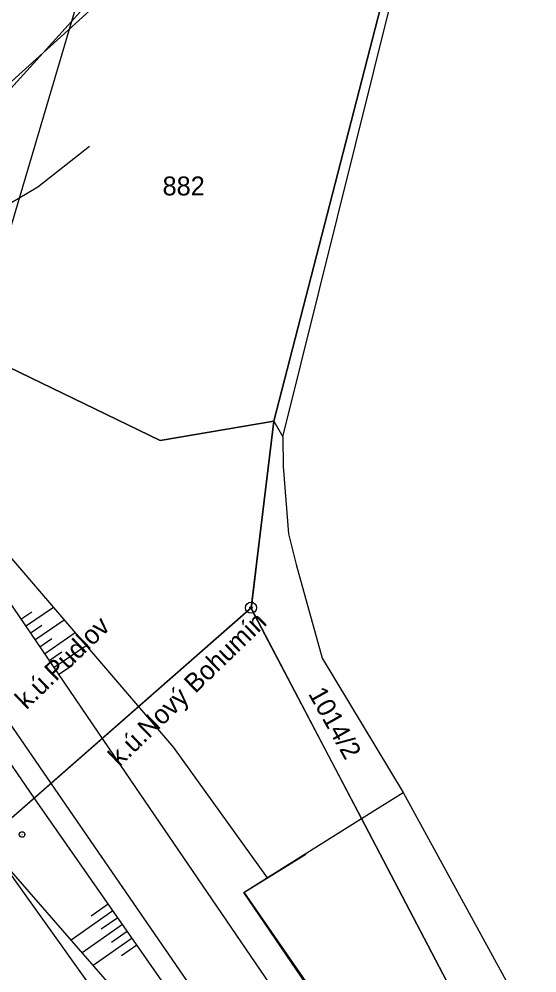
# Model space of a CAD drawing. Extents: x -469926 to -462499, y -1098642 to -1092733.
# Drawn here: x -465515.9 to -465469.3, y -1094927.6 to -1094841.9 of the extents above; entities that cross this region are included whole.
import ezdxf

# ---------------------------------------------------------------- set-up
doc = ezdxf.new("R2010")
doc.units = 0
for name, color, linetype in [('Vrstva 1', 7, 'Continuous'), ('Vrstva 10', 7, 'Continuous'), ('Vrstva 13', 7, 'Continuous'), ('Vrstva 14', 7, 'Continuous'), ('Vrstva 24', 7, 'Continuous'), ('Vrstva 4', 7, 'Continuous'), ('Vrstva 46', 7, 'Continuous'), ('Vrstva 48', 7, 'Continuous'), ('Vrstva 50', 7, 'Continuous'), ('Vrstva 6', 7, 'Continuous'), ('Vrstva 60', 7, 'Continuous'), ('Vrstva 8', 7, 'Continuous')]:
    doc.layers.add(name, color=color, linetype=linetype)

msp = doc.modelspace()

# ---------------------------------------------------------------- linework, layer by layer
at = {"layer": 'Vrstva 1'}
for p, q in [((-465513.71, -1094844.88), (-465507.9, -1094839.62)), ((-465530.47, -1094860.04), (-465513.71, -1094844.88)), ((-465503.18, -1094879.73), (-465516.78, -1094873.13)), ((-465492.98, -1094877.99), (-465503.18, -1094879.73)), ((-465492.98, -1094877.99), (-465492.15, -1094879.38)), ((-465492.15, -1094879.38), (-465492.13, -1094882.07)), ((-465492.13, -1094882.07), (-465491.64, -1094888.11)), ((-465491.64, -1094888.11), (-465490.96, -1094890.86)), ((-465490.96, -1094890.86), (-465488.63, -1094899.27)), ((-465485.09, -1094913.7), (-465495.02, -1094894.75)), ((-465488.63, -1094899.27), (-465481.34, -1094911.35)), ((-465485.09, -1094913.7), (-465481.34, -1094911.35)), ((-465481.34, -1094911.35), (-465461.75, -1094947.14)), ((-465495.65, -1094920.32), (-465485.09, -1094913.7)), ((-465468.49, -1094945.38), (-465485.09, -1094913.7)), ((-465430.6, -1095013.72), (-465495.65, -1094920.32))]:
    msp.add_line(p, q, dxfattribs=at)
at = {"layer": 'Vrstva 10'}
for points in [[(-465550.64, -1094835.27), (-465532.03, -1094861.45), (-465524.56, -1094863.32), (-465516.78, -1094873.13), (-465503.18, -1094879.73), (-465492.98, -1094877.99)], [(-465492.98, -1094877.99), (-465494.454, -1094890.101), (-465495.02, -1094894.85), (-465485.09, -1094913.7), (-465468.49, -1094945.38), (-465457.26, -1094963.68), (-465424.79, -1094990.33), (-465396.65, -1095009.33), (-465387.3, -1095015.62), (-465374.74, -1095024.26), (-465354.83, -1095034.77), (-465335.51, -1095045.09), (-465321.69, -1095051.49), (-465302.95, -1095060.17), (-465301.9, -1095057.95)]]:
    msp.add_lwpolyline(points, dxfattribs=at)
at = {"layer": 'Vrstva 13'}
for p, q in [((-465476.63, -1094814.73), (-465492.98, -1094877.99)), ((-465492.98, -1094877.99), (-465476.63, -1094814.73)), ((-465492.98, -1094877.99), (-465495.02, -1094894.75)), ((-465495.02, -1094894.75), (-465492.98, -1094877.99)), ((-465495.02, -1094894.75), (-465535.19, -1094929.97)), ((-465535.19, -1094929.97), (-465495.02, -1094894.75))]:
    msp.add_line(p, q, dxfattribs=at)
at = {"layer": 'Vrstva 14'}
msp.add_line((-465515.583, -1094915.147), (-465515.617, -1094915.113), dxfattribs=at)
msp.add_circle((-465515.6, -1094915.13), 0.25, dxfattribs=at)
at = {"layer": 'Vrstva 24'}
for radius in [0.5, 0.1]:
    msp.add_circle((-465495.02, -1094894.75), radius, dxfattribs=at)
at = {"layer": 'Vrstva 4'}
for p, q in [((-465492.15, -1094879.38), (-465479.79, -1094829.59)), ((-465513.71, -1094844.88), (-465508.71, -1094839.36)), ((-465528.07, -1094860.71), (-465513.71, -1094844.88))]:
    msp.add_line(p, q, dxfattribs=at)
at = {"layer": 'Vrstva 46'}
msp.add_lwpolyline([(-465340.639, -1095093.015), (-465346.12, -1095090.46), (-465348.87, -1095088.75), (-465361.32, -1095079.53), (-465373.61, -1095069.99), (-465387.88, -1095059.21), (-465398.49, -1095051.15), (-465402.84, -1095046.31), (-465413.86, -1095033.97), (-465425.21, -1095021.21), (-465428.98, -1095016.41), (-465440.31, -1094999.99), (-465453.18, -1094982.07), (-465481.39, -1094941.34), (-465488.11, -1094931.43), (-465495.66, -1094920.34), (-465490.1, -1094916.89)], dxfattribs=at)
at = {"layer": 'Vrstva 48'}
for p, q in [((-465515.709, -1094895.784), (-465514.737, -1094895.121)), ((-465515.287, -1094896.403), (-465512.787, -1094894.699)), ((-465514.864, -1094897.023), (-465513.837, -1094896.323)), ((-465514.442, -1094897.643), (-465511.804, -1094895.845)), ((-465513.598, -1094898.882), (-465510.822, -1094896.99)), ((-465514.02, -1094898.262), (-465512.937, -1094897.524)), ((-465513.175, -1094899.502), (-465512.037, -1094898.726)), ((-465512.753, -1094900.121), (-465509.839, -1094898.136)), ((-465512.33, -1094900.742), (-465511.137, -1094899.928)), ((-465507.433, -1094921.995), (-465511.204, -1094924.631)), ((-465507.863, -1094921.38), (-465509.397, -1094922.453)), ((-465507.003, -1094922.609), (-465508.485, -1094923.645)), ((-465506.573, -1094923.224), (-465510.212, -1094925.768)), ((-465505.714, -1094924.454), (-465509.22, -1094926.905)), ((-465506.144, -1094923.839), (-465507.573, -1094924.838)), ((-465505.284, -1094925.068), (-465506.66, -1094926.03))]:
    msp.add_line(p, q, dxfattribs=at)
at = {"layer": 'Vrstva 6'}
msp.add_line((-465517.87, -1094916.99), (-465500.09, -1094937.37), dxfattribs=at)
for points in [[(-465434.36, -1095026.37), (-465448.49, -1095009.06), (-465466.41, -1094985.15), (-465481.4, -1094961.47), (-465496.39, -1094937.79), (-465514.47, -1094911.93), (-465541.255, -1094872.83), (-465568.04, -1094833.73), (-465581.135, -1094814.86), (-465597.23, -1094791.03), (-465612.74, -1094768.15), (-465622.568, -1094754.33), (-465641.197, -1094726.93), (-465652.461, -1094710.94), (-465670.86, -1094684.36), (-465683.59, -1094665.34), (-465705.04, -1094634.71), (-465721.42, -1094610.27), (-465739.86, -1094583.31), (-465754.366, -1094564.659), (-465741.97, -1094582.27)], [(-465529, -1094860.39), (-465522.46, -1094861.8), (-465514.19, -1094856.92), (-465509.542, -1094853.275)], [(-465542.645, -1094856.19), (-465523.91, -1094883.75), (-465506.3, -1094909.59), (-465490.33, -1094932.99), (-465474.43, -1094956.03), (-465442.6, -1095002.04), (-465429.689, -1095019.75), (-465428.49, -1095021.29), (-465416.22, -1095035.84), (-465398.611, -1095054.406), (-465391.848, -1095060.089), (-465391.38, -1095060.44), (-465363.84, -1095082.26), (-465348.99, -1095091.83), (-465330.29, -1095102.47), (-465300.84, -1095115.8), (-465286.15, -1095121.03)], [(-465493.53, -1094919.018), (-465501.96, -1094907.32), (-465522.3, -1094883.61), (-465531.18, -1094871.802), (-465540.06, -1094859.993)], [(-465324.52, -1095121.16), (-465355.228, -1095103.306), (-465366.7, -1095096.22), (-465388.26, -1095080.92), (-465407.46, -1095064.389), (-465410.74, -1095061.49), (-465438.84, -1095028.81), (-465471.05, -1094987.83), (-465484.21, -1094964), (-465501.26, -1094940.2), (-465517.87, -1094916.99), (-465530.495, -1094898.64), (-465543.12, -1094880.29)]]:
    msp.add_lwpolyline(points, dxfattribs=at)
at = {"layer": 'Vrstva 60'}
msp.add_lwpolyline([(-465597.64, -1094787.45), (-465581.093, -1094811.54), (-465566.234, -1094833.14), (-465554.41, -1094850.35), (-465547.999, -1094859.66), (-465532.57, -1094882.09), (-465512.32, -1094911.53), (-465495.08, -1094936.61), (-465478.69, -1094960.45), (-465461.05, -1094986.11), (-465447.884, -1095005.16), (-465433.628, -1095024.45), (-465420.884, -1095039.67), (-465408.48, -1095052.76), (-465395.882, -1095064.54), (-465388.083, -1095071.147)], dxfattribs=at)
at = {"layer": 'Vrstva 8'}
msp.add_line((-465555.861, -1094992.932), (-465490.935, -1094773.91), dxfattribs=at)

# ---------------------------------------------------------------- texts
at = {"layer": 'Vrstva 50'}
msp.add_text('882', height=1.7, dxfattribs=at).set_placement((-465502.974, -1094857.7))
for s, rotation, p in [('k.ú.Nový Bohumín', 44.06081, (-465506.841, -1094909.106)), ('k.ú.Pudlov', 44.06081, (-465515.215, -1094903.968)), ('1014/2', 299.313, (-465489.921, -1094902.469))]:
    msp.add_text(s, height=1.7, rotation=rotation, dxfattribs=at).set_placement(p)

doc.saveas('drawing.dxf')
